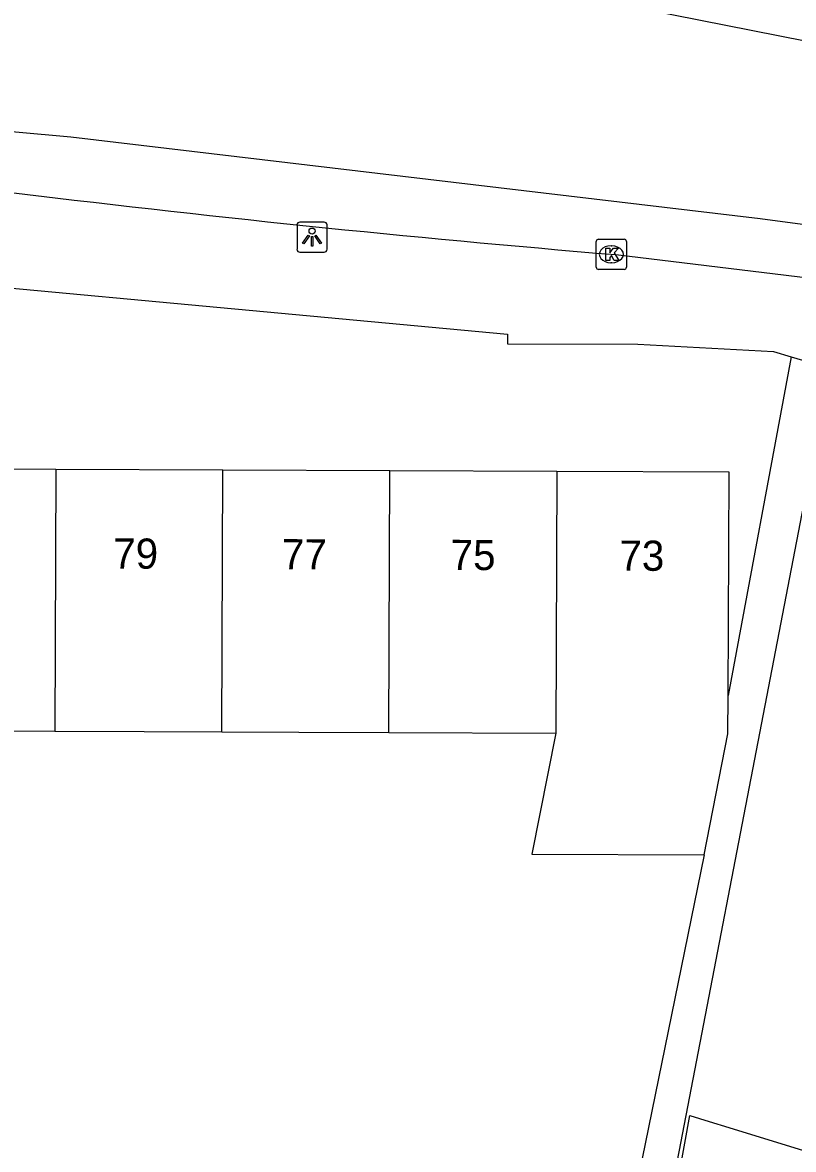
# Model space of a CAD drawing. Extents: x 163010 to 163853, y 382793 to 383982.
# Drawn here: x 163214.8 to 163240.37, y 383847.89 to 383885.27 of the extents above; entities that cross this region are included whole.
import ezdxf

# ---------------------------------------------------------------- set-up
doc = ezdxf.new("R2010")
doc.units = 0
for name, color, linetype in [('IMGEO_Kolk', 7, 'Continuous'), ('IMGEO_Lichtpunt', 7, 'Continuous'), ('IMGEO_Pand', 7, 'Continuous'), ('IMGEO_Pand_nummerreeks', 7, 'Continuous'), ('IMGEO_Rijbaan_lokaal_gesloten', 7, 'Continuous'), ('IMGEO_Voetpad_open', 7, 'Continuous')]:
    doc.layers.add(name, color=color, linetype=linetype)

msp = doc.modelspace()

# ---------------------------------------------------------------- linework, layer by layer
at = {"layer": 'IMGEO_Kolk'}
for p, q in [((163233.833, 383877.152), (163233.833, 383878.004)), ((163233.908, 383878.078), (163234.76, 383878.078)), ((163234.321, 383877.858), (163234.346, 383877.858)), ((163234.834, 383878.004), (163234.834, 383877.152)), ((163234.76, 383877.078), (163233.908, 383877.078)), ((163234.344, 383877.298), (163234.319, 383877.298))]:
    msp.add_line(p, q, dxfattribs=at)
for points in [[(163233.833, 383877.152), (163233.833, 383878.004)], [(163233.908, 383878.078), (163234.76, 383878.078)], [(163234.834, 383878.004), (163234.834, 383877.152)], [(163234.154, 383877.778), (163234.277, 383877.778), (163234.277, 383877.627), (163234.407, 383877.778), (163234.571, 383877.778), (163234.425, 383877.627), (163234.578, 383877.378), (163234.426, 383877.378), (163234.341, 383877.542), (163234.277, 383877.475), (163234.277, 383877.378), (163234.154, 383877.378), (163234.154, 383877.778)], [(163234.76, 383877.078), (163233.908, 383877.078)]]:
    msp.add_lwpolyline(points, dxfattribs=at)
for centre, start, end in [((163233.91, 383878.002), 91.552, 178.448), ((163233.91, 383878.002), 91.552, 178.448), ((163234.758, 383878.002), 1.552, 88.448), ((163234.758, 383878.002), 1.552, 88.448), ((163233.91, 383877.154), 181.552, 268.448), ((163233.91, 383877.154), 181.552, 268.448), ((163234.758, 383877.154), 271.552, 358.448), ((163234.758, 383877.154), 271.552, 358.448)]:
    msp.add_arc(centre, 0.0765, start, end, dxfattribs=at)
for centre, major_axis, ratio, start_param, end_param in [((163234.32, 383877.578), (-0.387, 0.002), 0.722429, 4.712389, 7.853982), ((163234.345, 383877.578), (-0.39, 0.002), 0.717154, 1.570796, 4.712389)]:
    msp.add_ellipse(centre, major_axis=major_axis, ratio=ratio, start_param=start_param, end_param=end_param, dxfattribs=at)
at = {"layer": 'IMGEO_Lichtpunt'}
for p, q in [((163224.809, 383878.645), (163224.001, 383878.645)), ((163224.809, 383878.645), (163224.001, 383878.645)), ((163223.907, 383878.55), (163223.907, 383877.743)), ((163223.907, 383878.55), (163223.907, 383877.743)), ((163224.903, 383877.743), (163224.903, 383878.55)), ((163224.903, 383877.743), (163224.903, 383878.55)), ((163224.001, 383877.649), (163224.809, 383877.649)), ((163224.001, 383877.649), (163224.809, 383877.649))]:
    msp.add_line(p, q, dxfattribs=at)
for points in [[(163224.281, 383878.214), (163224.32, 383878.186), (163224.132, 383877.924), (163224.094, 383877.951), (163224.281, 383878.214)], [(163224.493, 383878.186), (163224.531, 383878.213), (163224.718, 383877.951), (163224.679, 383877.923), (163224.493, 383878.186)], [(163224.383, 383878.166), (163224.43, 383878.166), (163224.43, 383877.844), (163224.383, 383877.844), (163224.383, 383878.166)]]:
    msp.add_lwpolyline(points, dxfattribs=at)
msp.add_circle((163224.406, 383878.348), 0.0994, dxfattribs=at)
for centre, start, end in [((163224.001, 383878.55), 90, 180), ((163224.001, 383878.55), 90, 180), ((163224.809, 383878.55), 0, 90), ((163224.809, 383878.55), 0, 90), ((163224.001, 383877.743), 180, 270), ((163224.001, 383877.743), 180, 270), ((163224.809, 383877.743), 270, 0), ((163224.809, 383877.743), 270, 360)]:
    msp.add_arc(centre, 0.0946, start, end, dxfattribs=at)
at = {"layer": 'IMGEO_Pand'}
for points in [[(163215.913, 383870.443), (163210.376, 383870.466)], [(163215.913, 383870.443), (163215.876, 383861.76)], [(163221.45, 383870.42), (163215.913, 383870.443)], [(163221.413, 383861.738), (163221.45, 383870.42)], [(163226.986, 383870.398), (163221.45, 383870.42)], [(163226.949, 383861.717), (163226.986, 383870.398)], [(163232.523, 383870.375), (163226.986, 383870.398)], [(163232.523, 383870.375), (163232.486, 383861.694)], [(163238.204, 383862.946), (163238.214, 383865.353), (163238.235, 383870.352), (163232.523, 383870.375)], [(163237.408, 383857.66), (163238.199, 383861.671), (163238.204, 383862.946)], [(163210.339, 383861.783), (163215.876, 383861.76)], [(163215.876, 383861.76), (163218.833, 383861.748), (163221.413, 383861.738)], [(163221.413, 383861.738), (163223.966, 383861.729), (163226.949, 383861.717)], [(163226.949, 383861.717), (163232.486, 383861.694)], [(163232.486, 383861.694), (163231.695, 383857.683), (163237.408, 383857.66)], [(163243.718, 383846.922), (163241.568, 383840.758), (163241.548, 383840.045), (163241.487, 383837.952), (163235.608, 383837.952), (163234.931, 383837.952), (163236.933, 383849.009), (163237.574, 383848.812), (163238.228, 383848.611), (163243.718, 383846.922)]]:
    msp.add_lwpolyline(points, dxfattribs=at)
at = {"layer": 'IMGEO_Rijbaan_lokaal_gesloten'}
for points in [[(163049.348, 383930.967), (163053.815, 383931.302), (163058.991, 383931.624), (163066.058, 383931.951), (163074.864, 383932.168), (163084.323, 383932.06), (163092.259, 383931.624), (163099.326, 383930.972), (163113.907, 383928.502), (163123.148, 383926.544), (163132.281, 383923.607), (163144.131, 383919.474), (163175.768, 383906.531), (163199.034, 383896.851), (163211.777, 383892.101), (163220.692, 383889.273), (163232.868, 383886.228), (163246.023, 383883.617), (163247.841, 383883.216)], [(163246.474, 383877.797), (163239.273, 383878.75), (163216.405, 383881.461), (163209.302, 383882.107), (163204.99, 383882.657), (163190.895, 383884.377)], [(163234.482, 383877.567), (163243.137, 383876.519)]]:
    msp.add_lwpolyline(points, dxfattribs=at)
msp.add_arc((163278.055, 384399.719), 523.967, 262.97374, 265.22979, dxfattribs=at)
at = {"layer": 'IMGEO_Voetpad_open'}
for points in [[(163204.223, 383877.406), (163230.891, 383874.924), (163230.886, 383874.604), (163235.215, 383874.595), (163239.71, 383874.352), (163240.298, 383874.177)], [(163240.298, 383874.177), (163238.204, 383862.946)], [(163240.298, 383874.177), (163241.573, 383873.797)], [(163241.573, 383873.797), (163234.649, 383837.824), (163247.996, 383837.824), (163247.996, 383836.131), (163245.959, 383836.178), (163243.141, 383836.199)], [(163237.408, 383857.66), (163234.053, 383841.193)]]:
    msp.add_lwpolyline(points, dxfattribs=at)

# ---------------------------------------------------------------- texts
at = {"layer": 'IMGEO_Pand_nummerreeks'}
for s, rotation, p in [('79', 359.7651, (163217.812, 383867.155)), ('77', 359.7651, (163223.407, 383867.132)), ('75', 359.7662, (163229.002, 383867.109)), ('73', 359.7651, (163234.598, 383867.086))]:
    msp.add_text(s, height=1, rotation=rotation, dxfattribs=at).set_placement(p)

doc.saveas('drawing.dxf')
